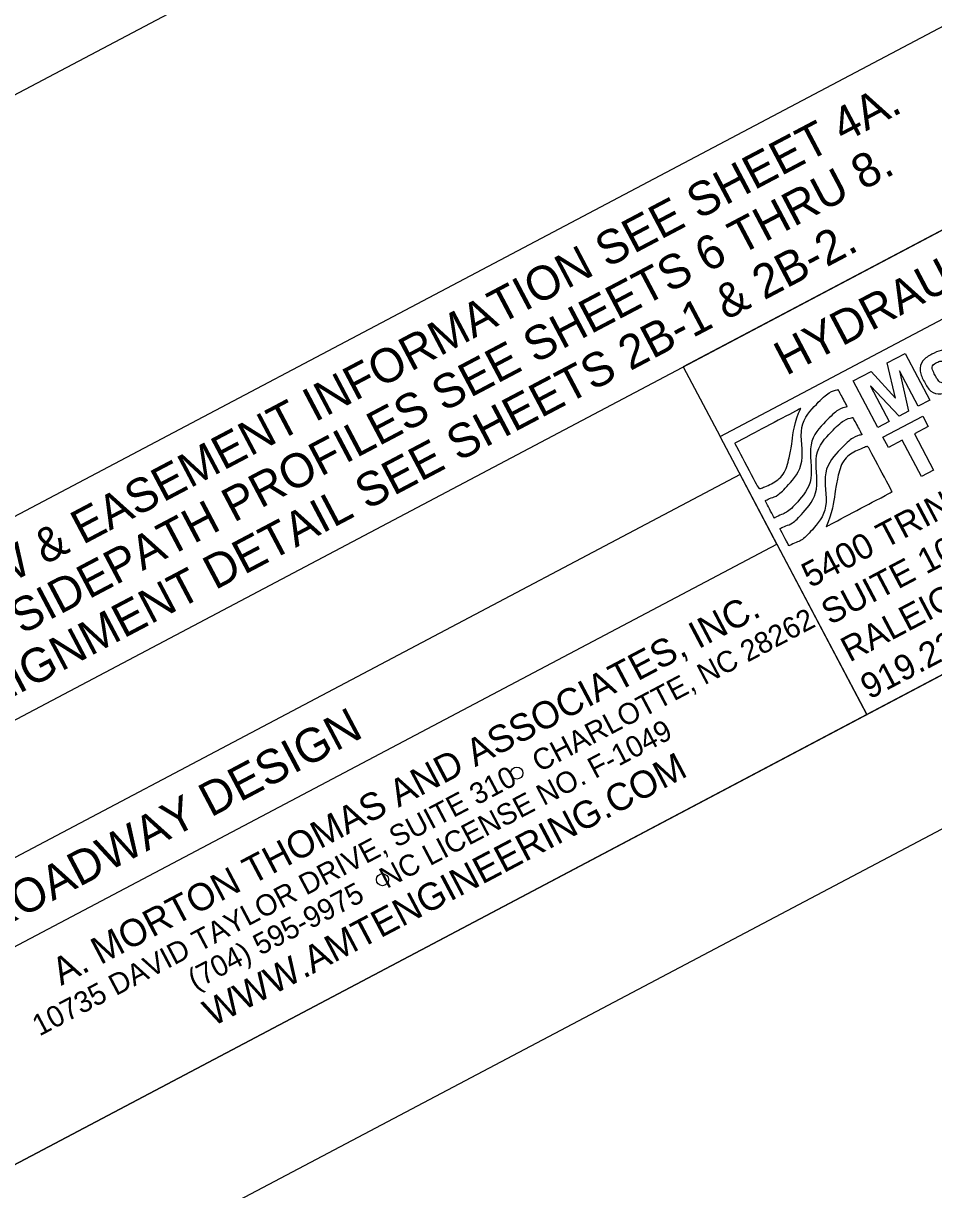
# Model space of a CAD drawing. Extents: x 1486990 to 1489232, y 497582 to 499336.
# Drawn here: x 1488796 to 1488946.8, y 498254 to 498447.2 of the extents above; entities that cross this region are included whole.
import ezdxf

# ---------------------------------------------------------------- set-up
doc = ezdxf.new("R2010")
doc.units = 0
for name, color, linetype in [('Prop Drainage Ditch Boundaries', 7, 'Continuous'), ('Prop Drainage Structure Catch Basin Open Throat 1 CELL', 7, 'Continuous'), ('Prop Drainage Structure Pipe Alternate 15in', 7, 'Continuous'), ('Prop Drainage Structure Plot Symbol 20 Scale', 7, 'Continuous'), ('Prop Earthen Structure V Ditch Berm Detail CELL', 7, 'Continuous'), ('Typical Terminator CELL', 7, 'Continuous')]:
    doc.layers.add(name, color=color, linetype=linetype)

msp = doc.modelspace()

# ---------------------------------------------------------------- linework, layer by layer
at = {"layer": 'Prop Drainage Ditch Boundaries'}
msp.add_lwpolyline([(1487562.23, 497581.96), (1489050.94, 498368.04), (1488539.66, 499336.34), (1487050.94, 498550.27)], close=True, dxfattribs=at)
at = {"layer": 'Prop Drainage Structure Catch Basin Open Throat 1 CELL'}
for points in [[(1488535.14, 499308.53), (1487208.67, 498608.12), (1487698.94, 497679.61), (1489025.4, 498380.01)], [(1487698.94, 497679.61), (1487208.66, 498608.09), (1488358.21, 499215.12), (1488428.29, 499082.43), (1488605.19, 499175.82), (1489025.4, 498380.01)]]:
    msp.add_lwpolyline(points, close=True, dxfattribs=at)
at = {"layer": 'Prop Drainage Structure Plot Symbol 20 Scale'}
msp.add_lwpolyline([(1487208.67, 498608.09), (1488222.08, 499143.23), (1488965.38, 498493.69), (1489025.4, 498380.01), (1487698.95, 497679.62)], close=True, dxfattribs=at)
at = {"layer": 'Prop Earthen Structure V Ditch Berm Detail CELL'}
for p, q in [((1488939.15, 498390.95), (1488942.11, 498392.52)), ((1488942.11, 498392.52), (1488946.18, 498384.8)), ((1488940.53, 498385.11), (1488939.15, 498390.95)), ((1488933.5, 498387.97), (1488936.46, 498389.54)), ((1488936.46, 498389.54), (1488940.51, 498385.09)), ((1488941.2, 498389.66), (1488941.18, 498389.65)), ((1488941.18, 498389.65), (1488942.65, 498382.93)), ((1488944.29, 498383.8), (1488941.2, 498389.66)), ((1488937.58, 498380.25), (1488933.5, 498387.97)), ((1488936.4, 498387.13), (1488936.38, 498387.11)), ((1488936.38, 498387.11), (1488939.47, 498381.25)), ((1488941.11, 498382.12), (1488936.4, 498387.13)), ((1488940.51, 498385.09), (1488940.53, 498385.11)), ((1488946.18, 498384.8), (1488944.29, 498383.8)), ((1488942.65, 498382.93), (1488941.11, 498382.12)), ((1488939.47, 498381.25), (1488937.58, 498380.25)), ((1488938.42, 498378.66), (1488945.04, 498382.15)), ((1488945.04, 498382.15), (1488945.95, 498380.42)), ((1488945.95, 498380.42), (1488943.65, 498379.2)), ((1488943.65, 498379.2), (1488946.81, 498373.21)), ((1488939.34, 498376.93), (1488938.42, 498378.66)), ((1488941.64, 498378.14), (1488939.34, 498376.93)), ((1488944.8, 498372.15), (1488941.64, 498378.14)), ((1488946.81, 498373.21), (1488944.8, 498372.15))]:
    msp.add_line(p, q, dxfattribs=at)
for points in [[(1488671.68, 498532.92), (1488879.76, 498642.79), (1488946.84, 498515.75), (1488738.76, 498405.88)], [(1488709.02, 498286.64), (1488994.97, 498437.63), (1488981.06, 498463.98), (1488695.11, 498312.99)], [(1488911.45, 498378.78), (1489001.06, 498426.1), (1488994.97, 498437.63), (1488905.36, 498390.32)], [(1488911.45, 498378.78), (1489001.06, 498426.1), (1489025.4, 498380.01), (1488935.79, 498332.69)], [(1488724.52, 498257.28), (1488920.87, 498360.95), (1488914.78, 498372.49), (1488718.43, 498268.81)], [(1488724.52, 498257.28), (1488920.87, 498360.95), (1488935.79, 498332.69), (1488739.44, 498229.02)]]:
    msp.add_lwpolyline(points, close=True, dxfattribs=at)
for points in [[(1488933.5, 498387.97), (1488936.46, 498389.54), (1488940.51, 498385.09), (1488940.53, 498385.11), (1488939.15, 498390.95), (1488942.11, 498392.52), (1488946.18, 498384.8), (1488944.29, 498383.8), (1488941.2, 498389.66), (1488941.18, 498389.65), (1488942.65, 498382.93), (1488941.11, 498382.12), (1488936.4, 498387.13), (1488936.38, 498387.11), (1488939.47, 498381.25), (1488937.58, 498380.25), (1488933.5, 498387.97)], [(1488945.95, 498380.42), (1488943.65, 498379.2), (1488946.81, 498373.21), (1488944.8, 498372.15), (1488941.64, 498378.14), (1488939.34, 498376.93), (1488938.42, 498378.66), (1488945.04, 498382.15), (1488945.95, 498380.42)]]:
    msp.add_lwpolyline(points, dxfattribs=at)
for points in [[(1488948.78, 498390.72), (1488948.52, 498391.19), (1488947.92, 498391.3), (1488947.46, 498391.06), (1488946.43, 498390.51), (1488946.73, 498389.55), (1488947.14, 498388.77), (1488947.52, 498388.05), (1488948.23, 498387.47), (1488949.01, 498387.88), (1488949.65, 498388.22), (1488949.78, 498388.76), (1488949.55, 498389.4), (1488949.55, 498389.4), (1488951.33, 498390.34), (1488951.33, 498390.34), (1488951.96, 498388.75), (1488951.25, 498387.27), (1488949.76, 498386.48), (1488948.07, 498385.59), (1488946.21, 498386.08), (1488945.3, 498387.8), (1488944.36, 498389.59), (1488944.82, 498391.46), (1488946.63, 498392.42), (1488948.02, 498393.15), (1488949.65, 498393.07), (1488950.56, 498391.66), (1488950.56, 498391.66), (1488948.78, 498390.72), (1488948.78, 498390.72)], [(1488948.78, 498390.72), (1488948.52, 498391.19), (1488947.92, 498391.3), (1488947.46, 498391.06), (1488946.43, 498390.51), (1488946.73, 498389.55), (1488947.14, 498388.77), (1488947.52, 498388.05), (1488948.23, 498387.47), (1488949.01, 498387.88), (1488949.65, 498388.22), (1488949.78, 498388.76), (1488949.55, 498389.4), (1488949.55, 498389.4), (1488951.33, 498390.34), (1488951.33, 498390.34), (1488951.96, 498388.75), (1488951.25, 498387.27), (1488949.76, 498386.48), (1488948.07, 498385.59), (1488946.21, 498386.08), (1488945.3, 498387.8), (1488944.36, 498389.59), (1488944.82, 498391.46), (1488946.63, 498392.42), (1488948.02, 498393.15), (1488949.65, 498393.07), (1488950.56, 498391.66), (1488950.56, 498391.66), (1488948.78, 498390.72), (1488948.78, 498390.72)], [(1488920.43, 498365.26), (1488921.42, 498365.79), (1488922.45, 498365.99), (1488924.02, 498367.58), (1488927.33, 498371.37), (1488925.65, 498377.82), (1488929.18, 498381.55), (1488931.11, 498383.39), (1488932.51, 498383.67), (1488932.51, 498383.67), (1488932.51, 498383.67), (1488931.01, 498386.52), (1488931.01, 498386.52), (1488931.01, 498386.52), (1488929.6, 498386.24), (1488927.67, 498384.4), (1488924.14, 498380.68), (1488925.82, 498374.22), (1488922.51, 498370.43), (1488920.94, 498368.85), (1488919.91, 498368.64), (1488918.92, 498368.12), (1488918.92, 498368.12), (1488920.43, 498365.26), (1488920.43, 498365.26)], [(1488920.43, 498365.26), (1488921.42, 498365.79), (1488922.45, 498365.99), (1488924.02, 498367.58), (1488927.33, 498371.37), (1488925.65, 498377.82), (1488929.18, 498381.55), (1488931.11, 498383.39), (1488932.51, 498383.67), (1488932.51, 498383.67), (1488932.51, 498383.67), (1488931.01, 498386.52), (1488931.01, 498386.52), (1488931.01, 498386.52), (1488929.6, 498386.24), (1488927.67, 498384.4), (1488924.14, 498380.68), (1488925.82, 498374.22), (1488922.51, 498370.43), (1488920.94, 498368.85), (1488919.91, 498368.64), (1488918.92, 498368.12), (1488918.92, 498368.12), (1488920.43, 498365.26), (1488920.43, 498365.26)], [(1488924.82, 498383.41), (1488923.79, 498381.28), (1488923.31, 498377.19), (1488923.02, 498375.84), (1488922.3, 498372.51), (1488920.3, 498370.97), (1488917.9, 498370.05), (1488917.9, 498370.05), (1488913.89, 498377.64), (1488913.89, 498377.64), (1488913.89, 498377.64), (1488924.82, 498383.41), (1488924.82, 498383.41)], [(1488924.82, 498383.41), (1488923.79, 498381.28), (1488923.31, 498377.19), (1488923.02, 498375.84), (1488922.3, 498372.51), (1488920.3, 498370.97), (1488917.9, 498370.05), (1488917.9, 498370.05), (1488913.89, 498377.64), (1488913.89, 498377.64), (1488913.89, 498377.64), (1488924.82, 498383.41), (1488924.82, 498383.41)], [(1488922.87, 498360.64), (1488923.86, 498361.17), (1488924.89, 498361.38), (1488926.46, 498362.96), (1488929.77, 498366.75), (1488928.09, 498373.21), (1488931.62, 498376.93), (1488933.54, 498378.77), (1488934.95, 498379.05), (1488934.95, 498379.05), (1488934.95, 498379.05), (1488933.44, 498381.91), (1488933.44, 498381.91), (1488933.44, 498381.91), (1488932.04, 498381.63), (1488930.11, 498379.79), (1488926.58, 498376.06), (1488928.26, 498369.61), (1488924.95, 498365.81), (1488923.38, 498364.23), (1488922.35, 498364.02), (1488921.36, 498363.5), (1488921.36, 498363.5), (1488922.87, 498360.64), (1488922.87, 498360.64)], [(1488922.87, 498360.64), (1488923.86, 498361.17), (1488924.89, 498361.38), (1488926.46, 498362.96), (1488929.77, 498366.75), (1488928.09, 498373.21), (1488931.62, 498376.93), (1488933.54, 498378.77), (1488934.95, 498379.05), (1488934.95, 498379.05), (1488934.95, 498379.05), (1488933.44, 498381.91), (1488933.44, 498381.91), (1488933.44, 498381.91), (1488932.04, 498381.63), (1488930.11, 498379.79), (1488926.58, 498376.06), (1488928.26, 498369.61), (1488924.95, 498365.81), (1488923.38, 498364.23), (1488922.35, 498364.02), (1488921.36, 498363.5), (1488921.36, 498363.5), (1488922.87, 498360.64), (1488922.87, 498360.64)], [(1488929.02, 498363.82), (1488930.05, 498365.95), (1488930.53, 498370.04), (1488930.82, 498371.39), (1488931.54, 498374.72), (1488933.55, 498376.26), (1488935.94, 498377.18), (1488935.94, 498377.18), (1488939.95, 498369.59), (1488939.95, 498369.59), (1488939.95, 498369.59), (1488929.02, 498363.82), (1488929.02, 498363.82)], [(1488929.02, 498363.82), (1488930.05, 498365.95), (1488930.53, 498370.04), (1488930.82, 498371.39), (1488931.54, 498374.72), (1488933.55, 498376.26), (1488935.94, 498377.18), (1488935.94, 498377.18), (1488939.95, 498369.59), (1488939.95, 498369.59), (1488939.95, 498369.59), (1488929.02, 498363.82), (1488929.02, 498363.82)]]:
    msp.add_open_spline(points, degree=3, dxfattribs=at)
at = {"layer": 'Typical Terminator CELL'}
msp.add_lwpolyline([(1488724.52, 498257.28), (1488920.87, 498360.95), (1488935.79, 498332.69), (1488739.44, 498229.02)], close=True, dxfattribs=at)
for centre in [(1488877.79, 498323.01), (1488855.54, 498305.36)]:
    msp.add_circle(centre, 1, dxfattribs=at)

# ---------------------------------------------------------------- texts
at = {"layer": 'Prop Drainage Structure Pipe Alternate 15in'}
for s, p in [('FOR ADDITIONAL ROW & EASEMENT INFORMATION SEE SHEET 4A.', (1488723.84, 498317.46)), ('HYDRAULIC DESIGN', (1488922.4, 498388.76)), ('FOR ROADWAY AND SIDEPATH PROFILES SEE SHEETS 6 THRU 8.', (1488727.78, 498310)), ('FOR -SIDEPATH- ALIGNMENT DETAIL SEE SHEETS 2B-1 & 2B-2.', (1488731.72, 498302.54)), ('ROADWAY DESIGN', (1488790.87, 498296.5))]:
    msp.add_text(s, height=5.625, rotation=27.8351, dxfattribs=at).set_placement(p)
at = {"layer": 'Prop Earthen Structure V Ditch Berm Detail CELL'}
for s, height, p in [('5400 TRINITY ROAD', 4.1773, (1488926.41, 498353.61)), ('919.223.8965   NC LIC. NO. F-1285', 4.1773, (1488936.17, 498335.14)), ('RALEIGH, NC 27607', 4.1773, (1488932.91, 498341.3)), ('SUITE 102', 4.177, (1488929.66, 498347.46))]:
    msp.add_text(s, height=height, rotation=27.8351, dxfattribs=at).set_placement(p)
at = {"layer": 'Typical Terminator CELL'}
for s, height, p in [('A. MORTON THOMAS AND ASSOCIATES, INC.', 4.5, (1488802.29, 498287.76)), ('10735 DAVID TAYLOR DRIVE, SUITE 310   CHARLOTTE, NC 28262', 3.5, (1488798.7, 498279.37)), ('(704) 595-9975   NC LICENSE NO. F-1049', 3.5, (1488824.48, 498287.04)), ('WWW.AMTENGINEERING.COM', 4.5, (1488827.4, 498280.95))]:
    msp.add_text(s, height=height, rotation=27.8346, dxfattribs=at).set_placement(p)

doc.saveas('drawing.dxf')
